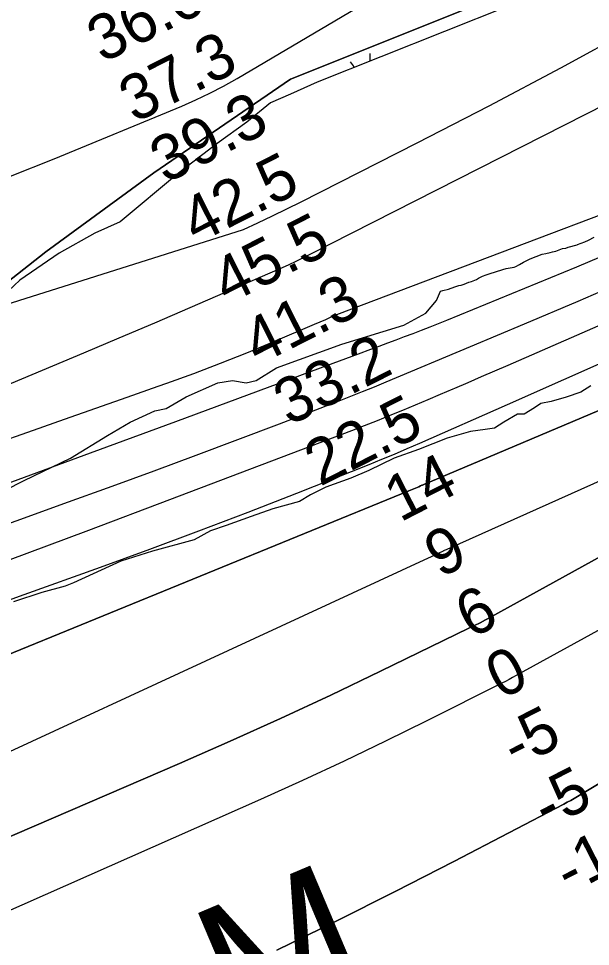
# Model space of a CAD drawing. Extents: x 3177385 to 3215275, y 903885 to 929304.
# Drawn here: x 3199010 to 3199851, y 915578 to 916943 of the extents above; entities that cross this region are included whole.
import ezdxf

# ---------------------------------------------------------------- set-up
doc = ezdxf.new("R2010")
doc.units = 0
for name, color, linetype in [('V-RIVR-EDGE', 7, 'Continuous'), ('V-RIVR-IDEN', 7, 'Continuous'), ('V-RIVR-RANG', 7, 'Continuous'), ('V-SITE-VEGE', 7, 'Continuous'), ('V-TOPO-DPTH', 7, 'Continuous'), ('V-TOPO-MAJR', 7, 'Continuous'), ('V-TOPO-MINR', 7, 'Continuous'), ('V-TOPO-WATR', 7, 'Continuous'), ('V-WETL-SWMP', 7, 'Continuous')]:
    doc.layers.add(name, color=color, linetype=linetype)

msp = doc.modelspace()

# ---------------------------------------------------------------- linework, layer by layer
at = {"layer": 'V-RIVR-EDGE'}
msp.add_lwpolyline([(3199852, 916402.6), (3199837.2, 916393.4), (3199815.5, 916386), (3199793.7, 916379.6), (3199778.5, 916376.9), (3199769.2, 916370.4), (3199754, 916361.2), (3199743.8, 916360.8), (3199723.9, 916349.3), (3199710.1, 916340.6), (3199696.7, 916338.3), (3199674.9, 916335.6), (3199640.7, 916325.5), (3199598.7, 916309), (3199562.6, 916296.1), (3199525.6, 916278.2), (3199498.8, 916266.7), (3199462.3, 916253.4), (3199439.6, 916242.4), (3199423.4, 916232.3), (3199384.1, 916221.7), (3199352.2, 916210.3), (3199315.7, 916197.4), (3199292.6, 916189.6), (3199268.6, 916176.3), (3199207.5, 916159.4), (3199160.9, 916144.7), (3199091, 916113), (3199079, 916108), (3199044.8, 916098.8), (3199003.2, 916085)], dxfattribs=at)
at = {"layer": 'V-SITE-VEGE'}
for points in [[(3200998.4, 917754.3), (3200829, 917658.9), (3200638.4, 917553), (3200310.2, 917362.3), (3200119.6, 917214), (3199727.9, 916981), (3199410.3, 916853.9), (3199209.2, 916716.1), (3199050.4, 916599.6), (3198902.1, 916483.1)], [(3199795.5, 916599.9), (3199800.3, 916600.9), (3199810.1, 916604.4), (3199814.9, 916605.3), (3199818.4, 916606.6), (3199831.7, 916609.8), (3199832.4, 916610.4), (3199843.2, 916614.2), (3199848.3, 916616.8), (3199856.5, 916621.2)], [(3198962.5, 916235.1), (3199018.8, 916263.2), (3199086.7, 916296.4), (3199141.3, 916329.5), (3199174.4, 916349.4), (3199210.9, 916365.9), (3199227.4, 916369.2), (3199256.8, 916386.6), (3199303.6, 916407.3), (3199325.1, 916410.6), (3199345, 916407.3), (3199359.9, 916410.6), (3199389.7, 916428.9), (3199485.8, 916463.7), (3199576.9, 916491.8), (3199609.2, 916509.6), (3199624.9, 916528.3), (3199630.8, 916541.7), (3199634, 916542.7), (3199642.6, 916544.9), (3199651.8, 916548.1), (3199657.9, 916550), (3199661, 916550.6), (3199665.5, 916552.2), (3199672.5, 916555.1), (3199676.3, 916556), (3199683.9, 916559.2), (3199686.8, 916560.8), (3199692.8, 916563.7), (3199697.9, 916565.9), (3199702.4, 916567.5), (3199722.4, 916573.8), (3199727.5, 916575.1), (3199738.9, 916577), (3199741.8, 916578), (3199746.9, 916581.1), (3199752.6, 916584.3), (3199762.4, 916589.4), (3199780.2, 916596.1), (3199785.6, 916597.4), (3199792, 916598.6), (3199795.5, 916599.9)]]:
    msp.add_lwpolyline(points, dxfattribs=at)
at = {"layer": 'V-TOPO-DPTH'}
for points in [[(3201016.8, 916777.3), (3200730.7, 916627.2), (3200720.2, 916621.7), (3200709.8, 916616.1), (3200699.3, 916610.6), (3200688.9, 916605), (3200678.5, 916599.4), (3200668.1, 916593.8), (3200657.7, 916588.2), (3200647.4, 916582.5), (3199705.1, 916062.9), (3199697, 916058.6), (3199689, 916054.3), (3199680.8, 916050.2), (3199672.6, 916046.1), (3199542.8, 915982.9), (3199469.4, 915947.8), (3199395.7, 915913.4), (3199321.6, 915879.9), (3199247.1, 915847.2), (3198765.9, 915639.7)], [(3198765.9, 915639.7), (3199247.1, 915847.2), (3199321.6, 915879.9), (3199395.7, 915913.4), (3199469.4, 915947.8), (3199542.8, 915982.9), (3199672.6, 916046.1), (3199680.8, 916050.2), (3199689, 916054.3), (3199697, 916058.6), (3199705.1, 916062.9), (3200647.4, 916582.5), (3200657.7, 916588.2), (3200668.1, 916593.8), (3200678.5, 916599.4), (3200688.9, 916605), (3200699.3, 916610.6), (3200709.8, 916616.1), (3200720.2, 916621.7), (3200730.7, 916627.2), (3201016.8, 916777.3)], [(3199947.6, 916527.8), (3199729.7, 916432.7), (3199710.1, 916424.2), (3199690.5, 916415.7), (3199670.9, 916407.2), (3199651.3, 916398.7), (3199649.1, 916397.7), (3199630.5, 916389.8), (3199612, 916381.9), (3199593.4, 916374.1), (3199574.8, 916366.4), (3199556.2, 916358.8), (3199537.5, 916351.3), (3199518.7, 916343.9), (3199499.9, 916336.7), (3199232.6, 916235.2), (3199113.2, 916190.1), (3198993.7, 916145.4)], [(3199863.5, 916366.3), (3199615.8, 916261.7), (3199612.9, 916260.5), (3199610.1, 916259.3), (3199607.2, 916258.1), (3199604.4, 916256.8), (3199603.6, 916256.5), (3199601.2, 916255.4), (3199598.8, 916254.3), (3199596.3, 916253.3), (3199593.9, 916252.2), (3199591.5, 916251.1), (3199589.1, 916250.1), (3199586.6, 916249.1), (3199584.2, 916248.1), (3198970.2, 915997.4)], [(3198970.2, 915997.4), (3199584.2, 916248.1), (3199586.6, 916249.1), (3199589.1, 916250.1), (3199591.5, 916251.1), (3199593.9, 916252.2), (3199596.3, 916253.3), (3199598.8, 916254.3), (3199601.2, 916255.4), (3199603.6, 916256.5), (3199604.4, 916256.8), (3199607.2, 916258.1), (3199610.1, 916259.3), (3199612.9, 916260.5), (3199615.8, 916261.7), (3199863.5, 916366.3)], [(3199390.3, 915572.8), (3199477.4, 915615.5), (3199564, 915659.1), (3199650.3, 915703.3), (3199812.1, 915787.4), (3199817.2, 915790.1), (3199822.3, 915792.9), (3199827.4, 915795.8), (3199832.4, 915798.8), (3199924.4, 915854)], [(3199390.3, 915572.8), (3199477.4, 915615.5), (3199564, 915659.1), (3199650.3, 915703.3), (3199812.1, 915787.4), (3199817.2, 915790.1), (3199822.3, 915792.9), (3199827.4, 915795.8), (3199832.4, 915798.8), (3199924.4, 915854)]]:
    msp.add_lwpolyline(points, dxfattribs=at)
at = {"layer": 'V-TOPO-MAJR'}
for points in [[(3198998.4, 916711.2), (3199062.6, 916736.6), (3199250.3, 916814.1), (3199271.2, 916823.2), (3199291.7, 916832.9), (3199311.8, 916843.5), (3199331.7, 916854.6), (3200142, 917333.4), (3200155.3, 917341.4), (3200168.4, 917349.6), (3200181.4, 917358), (3200194.3, 917366.6), (3200207.1, 917375.4), (3200219.8, 917384.3), (3200232.4, 917393.3), (3200244.9, 917402.4), (3200772.4, 917691)], [(3200164.6, 916766.8), (3199477.9, 916507.3), (3199469.8, 916503.6), (3199461.6, 916499.9), (3199453.4, 916496.3), (3199445.2, 916492.8), (3199384.5, 916466.9), (3199345.7, 916450.9), (3199306.8, 916435.3), (3199267.5, 916420.5), (3199228.1, 916406.2), (3199215.4, 916401.8), (3199169.5, 916385.6), (3199123.6, 916369.5), (3199077.7, 916353.3), (3199031.9, 916337.1), (3198908.7, 916293.6)]]:
    msp.add_lwpolyline(points, dxfattribs=at)
at = {"layer": 'V-TOPO-MINR'}
for points in [[(3198680.1, 916423.5), (3199341, 916632.8), (3199362.4, 916642.6), (3199383.8, 916652.5), (3199404.9, 916662.8), (3199426, 916673.3), (3199596.5, 916759.8), (3199702.4, 916814.4), (3199807.8, 916870.1), (3199912.3, 916927.2), (3200016.4, 916985.2), (3200317.9, 917156.3), (3200335.2, 917166.3), (3200352.3, 917176.6), (3200369.3, 917187.1), (3200386.1, 917197.8), (3200958.3, 917570.4), (3201001.6, 917598.9), (3201044.9, 917627.6), (3201087.9, 917656.7), (3201130.7, 917686)], [(3200141, 916953.9), (3200052.3, 916908.2), (3199963.6, 916862.7), (3199874.8, 916817.4), (3199437.9, 916595.1), (3199428, 916590.2), (3199418, 916585.4), (3199407.9, 916580.7), (3199397.8, 916576.2), (3199314.3, 916539.7), (3199262.3, 916517.2), (3199210.2, 916494.8), (3199158, 916472.6), (3199105.8, 916450.5), (3198421.9, 916163.7)], [(3201016.8, 916777.3), (3200730.7, 916627.2), (3200720.2, 916621.7), (3200709.8, 916616.1), (3200699.3, 916610.6), (3200688.9, 916605), (3200678.5, 916599.4), (3200668.1, 916593.8), (3200657.7, 916588.2), (3200647.4, 916582.5), (3199705.1, 916062.9), (3199697, 916058.6), (3199689, 916054.3), (3199680.8, 916050.2), (3199672.6, 916046.1), (3199542.8, 915982.9), (3199469.4, 915947.8), (3199395.7, 915913.4), (3199321.6, 915879.9), (3199247.1, 915847.2), (3198765.9, 915639.7)], [(3199937.9, 916622.9), (3199830.8, 916577.1), (3199639.6, 916498.7), (3199627.3, 916493.7), (3199615, 916488.8), (3199602.5, 916484), (3199590.1, 916479.3), (3199577.6, 916474.6), (3199565.2, 916470), (3199552.7, 916465.3), (3199540.3, 916460.6), (3199528.1, 916456), (3199509.6, 916449.1), (3199491.1, 916442.2), (3199472.5, 916435.3), (3199454, 916428.4), (3199241, 916349.7), (3199115.9, 916303.6), (3198990.8, 916257.6)], [(3199911.6, 916561.1), (3199832.8, 916526.9), (3199753.7, 916493.2), (3199674.5, 916459.8), (3199550.4, 916407.8), (3199533.2, 916400.7), (3199515.8, 916393.7), (3199498.5, 916386.8), (3199481.1, 916380), (3199393.5, 916346.4), (3199332.2, 916323.1), (3199270.9, 916300), (3199209.3, 916277.3), (3199147.7, 916254.8), (3199076.3, 916229), (3199013.1, 916206.2), (3198949.8, 916183.4)], [(3199947.6, 916527.8), (3199729.7, 916432.7), (3199710.1, 916424.2), (3199690.5, 916415.7), (3199670.9, 916407.2), (3199651.3, 916398.7), (3199649.1, 916397.7), (3199630.5, 916389.8), (3199612, 916381.9), (3199593.4, 916374.1), (3199574.8, 916366.4), (3199556.2, 916358.8), (3199537.5, 916351.3), (3199518.7, 916343.9), (3199499.9, 916336.7), (3199232.6, 916235.2), (3199113.2, 916190.1), (3198993.7, 916145.4)], [(3200611.3, 916454.2), (3199742.1, 915976.4), (3199736.8, 915973.6), (3199731.6, 915970.8), (3199726.3, 915968), (3199721, 915965.3), (3199610.7, 915910), (3199550.1, 915880.1), (3199489.1, 915850.8), (3199427.8, 915822.4), (3199366.2, 915794.5), (3198762.4, 915527)], [(3199894.4, 916448.4), (3199811.7, 916411.3), (3199728.8, 916374.5), (3199599.9, 916317.8), (3199581.3, 916309.8), (3199562.7, 916301.9), (3199544, 916294.1), (3199525.2, 916286.6), (3199419.2, 916244.5), (3199347.3, 916216.4), (3199275.2, 916188.7), (3199202.8, 916161.8), (3199130.2, 916135.4), (3199018, 916095.1), (3198964.6, 916076)], [(3199986.9, 916317.4), (3199640.3, 916162), (3199639.3, 916161.6), (3199636.3, 916160.3), (3199635.2, 916159.8), (3199635, 916159.7), (3199634.8, 916159.6), (3199627.6, 916156.2), (3199623.8, 916154.5), (3199620, 916152.7), (3199616.3, 916150.9), (3199612.5, 916149.2), (3198662.8, 915710)], [(3199924.4, 915854), (3199832.4, 915798.8), (3199827.4, 915795.8), (3199822.3, 915792.9), (3199817.2, 915790.1), (3199812.1, 915787.4), (3199650.3, 915703.3), (3199564, 915659.1), (3199477.4, 915615.5), (3199390.3, 915572.8)]]:
    msp.add_lwpolyline(points, dxfattribs=at)
at = {"layer": 'V-TOPO-WATR'}
msp.add_lwpolyline([(3199863.5, 916366.3), (3199615.8, 916261.7), (3199612.9, 916260.5), (3199610.1, 916259.3), (3199607.2, 916258.1), (3199604.4, 916256.8), (3199603.6, 916256.5), (3199601.2, 916255.4), (3199598.8, 916254.3), (3199596.3, 916253.3), (3199593.9, 916252.2), (3199591.5, 916251.1), (3199589.1, 916250.1), (3199586.6, 916249.1), (3199584.2, 916248.1), (3198970.2, 915997.4)], dxfattribs=at)
at = {"layer": 'V-WETL-SWMP'}
msp.add_line((3199527.2, 916880.3), (3199527.2, 916891.6), dxfattribs=at)
for points in [[(3201209.9, 917838.5), (3200877.8, 917671.1), (3200503.4, 917443.1), (3199949.6, 917086.9), (3199730.2, 916961), (3199449.6, 916849.5), (3199410.1, 916831.5), (3199380.8, 916818.8), (3199345.9, 916790.2), (3199302.2, 916759.2), (3199245.8, 916715.5), (3199160, 916644), (3199122.7, 916627.3), (3199070.3, 916597.9), (3199012.3, 916558.2), (3198978.4, 916526.6)], [(3198902.1, 916483.1), (3199050.4, 916599.6), (3199209.2, 916716.1), (3199410.3, 916853.9), (3199727.9, 916981), (3200119.6, 917214), (3200310.2, 917362.3), (3200638.4, 917553), (3200829, 917658.9), (3200998.4, 917754.3)]]:
    msp.add_lwpolyline(points, dxfattribs=at)
msp.add_arc((3199471.9, 916856.2), 35.2, 24.8738, 40.6385, dxfattribs=at)

# ---------------------------------------------------------------- texts
at = {"layer": 'V-RIVR-IDEN'}
msp.add_text('M', height=200, rotation=22.9461, dxfattribs=at).set_placement((3199332.2, 915434.6))
at = {"layer": 'V-RIVR-RANG'}
for s, rotation, p in [('36.6', 26.8883, (3199133.9, 916876.7)), ('37.3', 26.8883, (3199181, 916788.5)), ('39.3', 26.8883, (3199226.5, 916699.4)), ('42.5', 26.8883, (3199271.9, 916610.3)), ('45.5', 26.8883, (3199317.4, 916521.3)), ('41.3', 26.8883, (3199362.8, 916432.2)), ('33.2', 26.8883, (3199408.3, 916343.1)), ('22.5', 26.8883, (3199453.7, 916254)), ('14', 27.1739, (3199571.4, 916201.4)), ('9', 27.1739, (3199630.4, 916119.3)), ('6', 27.1739, (3199675.6, 916030.1)), ('0', 27.1739, (3199720.4, 915940.7)), ('-5', 27.1739, (3199741.7, 915839.2)), ('-5', 27.1739, (3199787.1, 915750.1)), ('-10', 27.1739, (3199819.7, 915654.4))]:
    msp.add_text(s, height=67, rotation=rotation, dxfattribs=at).set_placement(p)

doc.saveas('drawing.dxf')
